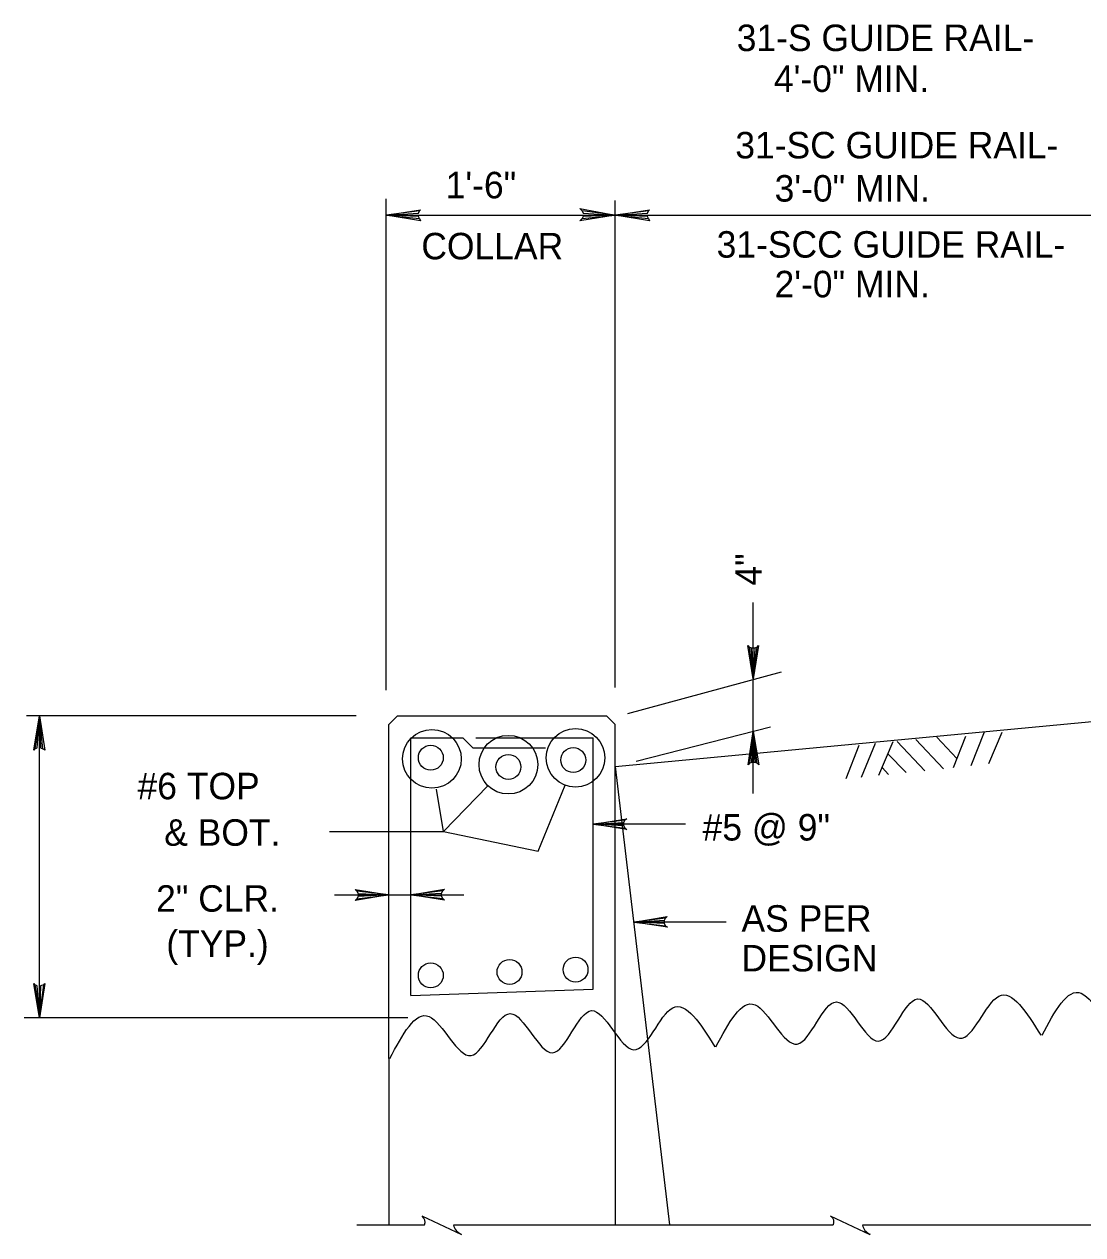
# Model space of a CAD drawing. Extents: x 639011 to 639866, y 298840 to 300028.
# Drawn here: x 639398.2 to 639518, y 298939.1 to 299076.2 of the extents above; entities that cross this region are included whole.
import ezdxf

# ---------------------------------------------------------------- set-up
doc = ezdxf.new("R2010")
doc.units = 0
doc.layers.add('2', color=7, linetype='Continuous')

msp = doc.modelspace()

# ---------------------------------------------------------------- linework, layer by layer
at = {"layer": '2'}
for p, q in [((639439.2, 299000.8), (639439.2, 299056.41)), ((639465.12, 299001.08), (639465.12, 299056.24)), ((639439.2, 299054.56), (639465.12, 299054.56)), ((639457.04, 299054.56), (639465.12, 299054.56)), ((639465.12, 299054.56), (639538.17, 299054.56)), ((639480.73, 299002.07), (639480.73, 299010.71)), ((639480.73, 299003.74), (639480.73, 299007.64)), ((639465.12, 298992.16), (639607.78, 299005.6)), ((639480.73, 299002.07), (639480.1, 299005.86)), ((639480.1, 299005.86), (639480.27, 299005.66)), ((639480.53, 299005.54), (639480.27, 299005.66)), ((639480.27, 299005.66), (639480.73, 299002.07)), ((639480.73, 299002.07), (639480.53, 299005.54)), ((639480.9, 299005.54), (639480.53, 299005.54)), ((639480.73, 299002.07), (639480.71, 299005.54)), ((639481.32, 299005.87), (639480.73, 299002.07)), ((639480.73, 299002.07), (639481.16, 299005.68)), ((639480.9, 299005.54), (639480.73, 299002.07)), ((639481.16, 299005.68), (639480.9, 299005.54)), ((639481.16, 299005.68), (639481.32, 299005.87)), ((639466.52, 298998.16), (639483.91, 299002.87)), ((639480.73, 298989.1), (639480.73, 299002.01)), ((639435.8, 298997.89), (639398.49, 298997.89)), ((639399.94, 298963.7), (639399.94, 298997.89)), ((639439.48, 298996.89), (639440.48, 298997.89)), ((639439.48, 298959.09), (639439.48, 298996.89)), ((639440.48, 298997.89), (639464.12, 298997.89)), ((639464.12, 298997.89), (639465.12, 298996.89)), ((639465.12, 298961.86), (639465.12, 298996.89)), ((639441.99, 298966.24), (639441.99, 298995.38)), ((639441.99, 298995.38), (639447.88, 298995.38)), ((639447.88, 298995.38), (639448.99, 298994.26)), ((639449.32, 298995.38), (639462.61, 298995.38)), ((639462.61, 298966.96), (639462.61, 298995.38)), ((639467.47, 298992.76), (639482.68, 298996.63)), ((639480.14, 298992.33), (639480.73, 298996.13)), ((639480.73, 298996.13), (639480.3, 298992.52)), ((639480.56, 298992.66), (639480.73, 298996.13)), ((639480.73, 298996.13), (639480.93, 298992.66)), ((639481.19, 298992.53), (639480.73, 298996.13)), ((639480.73, 298996.13), (639481.36, 298992.34)), ((639480.73, 298996.13), (639480.75, 298992.66)), ((639501.5, 298995.47), (639503.77, 298993.07)), ((639504.76, 298995.56), (639503.37, 298992.02)), ((639506.85, 298996.03), (639505.36, 298992.23)), ((639508.86, 298995.99), (639507.35, 298992.44)), ((639448.99, 298994.26), (639457.21, 298994.26)), ((639492.68, 298994.54), (639491.19, 298990.74)), ((639494.54, 298994.74), (639492.93, 298990.92)), ((639496.53, 298994.94), (639494.92, 298991.13)), ((639497.03, 298995), (639500.14, 298991.68)), ((639499.14, 298995.22), (639502.25, 298991.9)), ((639480.3, 298992.52), (639480.56, 298992.66)), ((639480.56, 298992.66), (639480.93, 298992.66)), ((639480.93, 298992.66), (639481.19, 298992.53)), ((639481.36, 298992.34), (639481.19, 298992.53)), ((639495.92, 298993.62), (639498.03, 298991.46)), ((639465.12, 298992.16), (639471.26, 298940.26)), ((639480.3, 298992.52), (639480.14, 298992.33)), ((639495.33, 298992.05), (639496.04, 298991.25)), ((639445.68, 298984.79), (639450.71, 298989.98)), ((639456.39, 298982.58), (639459.43, 298990.05)), ((639445.68, 298984.79), (639444.89, 298989.6)), ((639462.61, 298985.61), (639466.41, 298986.24)), ((639466.21, 298986.07), (639462.61, 298985.61)), ((639462.61, 298985.61), (639466.09, 298985.81)), ((639466.09, 298985.81), (639466.21, 298986.07)), ((639466.09, 298985.44), (639466.09, 298985.81)), ((639466.41, 298986.24), (639466.21, 298986.07)), ((639432.78, 298984.79), (639445.68, 298984.79)), ((639445.68, 298984.79), (639456.39, 298982.58)), ((639462.61, 298985.61), (639466.09, 298985.62)), ((639473.06, 298985.61), (639462.61, 298985.61)), ((639466.09, 298985.44), (639462.61, 298985.61)), ((639462.61, 298985.61), (639466.22, 298985.18)), ((639466.42, 298985.02), (639462.61, 298985.61)), ((639466.22, 298985.18), (639466.09, 298985.44)), ((639466.22, 298985.18), (639466.42, 298985.02)), ((639433.36, 298977.62), (639439.48, 298977.62)), ((639435.87, 298978.05), (639435.68, 298978.21)), ((639435.68, 298978.21), (639439.48, 298977.62)), ((639439.48, 298977.62), (639435.69, 298976.99)), ((639435.87, 298978.05), (639436.01, 298977.79)), ((639439.48, 298977.62), (639435.87, 298978.05)), ((639435.88, 298977.17), (639439.48, 298977.62)), ((639436.01, 298977.79), (639439.48, 298977.62)), ((639436.01, 298977.79), (639436.01, 298977.43)), ((639439.48, 298977.62), (639436.01, 298977.43)), ((639439.48, 298977.62), (639436.01, 298977.61)), ((639439.48, 298977.62), (639441.99, 298977.62)), ((639441.99, 298977.62), (639445.78, 298978.26)), ((639445.59, 298978.08), (639441.99, 298977.62)), ((639441.99, 298977.62), (639445.46, 298977.82)), ((639441.99, 298977.62), (639445.46, 298977.64)), ((639441.99, 298977.62), (639447.96, 298977.62)), ((639445.46, 298977.46), (639441.99, 298977.62)), ((639441.99, 298977.62), (639445.6, 298977.19)), ((639445.79, 298977.03), (639441.99, 298977.62)), ((639445.46, 298977.82), (639445.59, 298978.08)), ((639445.46, 298977.46), (639445.46, 298977.82)), ((639445.6, 298977.19), (639445.46, 298977.46)), ((639445.78, 298978.26), (639445.59, 298978.08)), ((639435.69, 298976.99), (639435.88, 298977.17)), ((639436.01, 298977.43), (639435.88, 298977.17)), ((639445.6, 298977.19), (639445.79, 298977.03)), ((639467.2, 298974.54), (639471, 298975.18)), ((639470.8, 298975), (639467.2, 298974.54)), ((639467.2, 298974.54), (639470.68, 298974.74)), ((639470.68, 298974.74), (639470.8, 298975)), ((639470.68, 298974.38), (639470.68, 298974.74)), ((639471, 298975.18), (639470.8, 298975)), ((639467.2, 298974.54), (639470.68, 298974.56)), ((639477.65, 298974.54), (639467.2, 298974.54)), ((639470.68, 298974.38), (639467.2, 298974.54)), ((639467.2, 298974.54), (639470.81, 298974.11)), ((639471.01, 298973.95), (639467.2, 298974.54)), ((639470.81, 298974.11), (639470.68, 298974.38)), ((639470.81, 298974.11), (639471.01, 298973.95)), ((639441.99, 298966.24), (639462.61, 298966.96)), ((639441.63, 298963.7), (639398.23, 298963.7)), ((639465.12, 298961.86), (639465.12, 298940.26)), ((639439.48, 298959.09), (639439.48, 298940.26)), ((639447.75, 298939.13), (639443.25, 298941.26)), ((639493.98, 298939.14), (639489.48, 298941.26)), ((639435.88, 298940.26), (639443.53, 298940.26)), ((639446.81, 298940.26), (639489.79, 298940.26)), ((639493.08, 298940.26), (639536.05, 298940.26))]:
    msp.add_line(p, q, dxfattribs=at)
for points in [[(639442.95, 299054.19), (639442.83, 299054.44), (639439.2, 299054.56), (639442.95, 299054.19), (639443.08, 299053.94), (639439.2, 299054.56), (639442.83, 299054.81), (639442.95, 299055.06), (639439.2, 299054.56), (639443.08, 299055.19), (639442.95, 299055.06)], [(639461.37, 299055.06), (639461.5, 299054.81), (639465.12, 299054.56), (639461.37, 299055.06), (639461.12, 299055.31), (639465.12, 299054.56), (639461.5, 299054.44), (639461.37, 299054.19), (639465.12, 299054.56), (639461.12, 299053.94), (639461.37, 299054.19)], [(639468.87, 299054.19), (639468.75, 299054.44), (639465.12, 299054.56), (639468.87, 299054.19), (639469, 299053.94), (639465.12, 299054.56), (639468.75, 299054.81), (639468.87, 299055.06), (639465.12, 299054.56), (639469, 299055.19), (639468.87, 299055.06)], [(639399.44, 298994.14), (639399.69, 298994.26), (639399.94, 298997.89), (639399.44, 298994.14), (639399.32, 298994.01), (639399.94, 298997.89), (639400.07, 298994.26), (639400.32, 298994.14), (639399.94, 298997.89), (639400.57, 298994.01), (639400.32, 298994.14)], [(639400.44, 298967.45), (639400.07, 298967.32), (639399.94, 298963.7), (639400.44, 298967.45), (639400.57, 298967.57), (639399.94, 298963.7), (639399.69, 298967.32), (639399.44, 298967.45), (639399.94, 298963.7), (639399.32, 298967.57), (639399.44, 298967.45)]]:
    msp.add_lwpolyline(points, dxfattribs=at)
for centre, radius in [((639444.37, 298993.01), 3.32), ((639453.02, 298992.36), 3.32), ((639460.62, 298993.14), 3.32), ((639444.24, 298993.14), 1.41), ((639460.36, 298992.88), 1.41), ((639453.02, 298992.1), 1.41), ((639444.24, 298968.5), 1.41), ((639453.15, 298968.89), 1.41), ((639460.62, 298969.16), 1.41)]:
    msp.add_circle(centre, radius, dxfattribs=at)
for centre in [(639442.83, 298940.59), (639489.1, 298940.59)]:
    msp.add_arc(centre, 0.767, 335.2452, 53.2548, dxfattribs=at)
for centre in [(639448.59, 298940.54), (639494.86, 298940.54)]:
    msp.add_ellipse(centre, major_axis=(-1.77, -0.3), ratio=0.84059, start_param=0.001606, end_param=0.896554, dxfattribs=at)
for points in [[(639513.41, 298961.72), (639517.85, 298966.48), (639522.61, 298962.05), (639527.04, 298966.81), (639531.8, 298962.38), (639536.24, 298967.14), (639541, 298962.71), (639545.43, 298967.47), (639550.19, 298963.03)], [(639476.51, 298960.41), (639480.94, 298965.17), (639485.71, 298960.73), (639490.14, 298965.5), (639494.9, 298961.06), (639499.33, 298965.83), (639504.09, 298961.39), (639508.53, 298966.15), (639513.29, 298961.72)], [(639439.61, 298959.09), (639444.04, 298963.85), (639448.8, 298959.42), (639453.23, 298964.18), (639458, 298959.75), (639462.43, 298964.51), (639467.19, 298960.08), (639471.62, 298964.84), (639476.38, 298960.41)]]:
    msp.add_spline(points, degree=3, dxfattribs=at)

# ---------------------------------------------------------------- texts
for s, p in [('31-S GUIDE RAIL-', (639478.86, 299073.15)), ('4\'-0" MIN.', (639483.07, 299068.52)), ('31-SC GUIDE RAIL-', (639478.7, 299061)), ('1\'-6"', (639445.92, 299056.48)), ('3\'-0" MIN.', (639483.15, 299056.11)), ('COLLAR', (639443.17, 299049.57)), ('31-SCC GUIDE RAIL-', (639476.59, 299049.76)), ('2\'-0" MIN.', (639483.14, 299045.27)), ('#6 TOP', (639411.05, 298988.44)), ('& BOT.', (639414.07, 298983.18)), ('#5 @ 9"', (639475, 298983.77)), ('2" CLR.', (639413.15, 298975.71)), ('AS PER', (639479.4, 298973.45)), ('(TYP.)', (639414.31, 298970.6)), ('DESIGN', (639479.4, 298968.95))]:
    msp.add_text(s, height=3, dxfattribs=at).set_placement(p)
msp.add_text('4"', height=3, rotation=90, dxfattribs=at).set_placement((639481.69, 299012.63))

doc.saveas('drawing.dxf')
